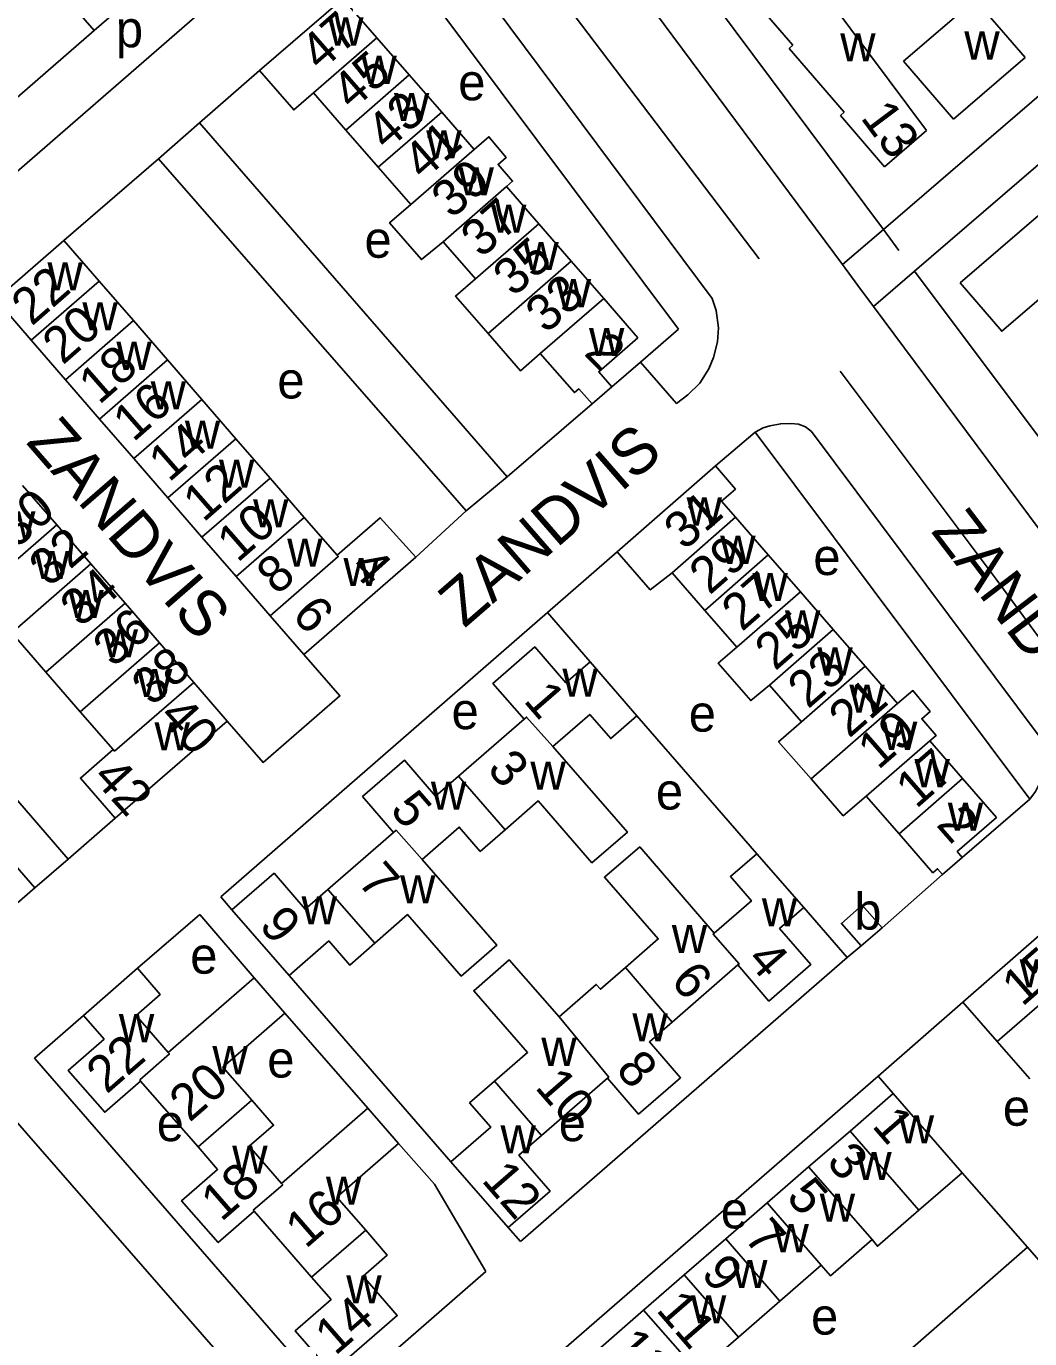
# Model space of a CAD drawing. Extents: x 155854 to 157362, y 383621 to 384685.
# Drawn here: x 156659.8 to 156769.5, y 384304.4 to 384447.9 of the extents above; entities that cross this region are included whole.
import ezdxf

# ---------------------------------------------------------------- set-up
doc = ezdxf.new("R2010")
doc.units = 0
for name, color, linetype in [('BLT_Basislijn', 7, 'Continuous'), ('BLT_Bebouwing', 7, 'Continuous'), ('BLT_Centroide', 7, 'Continuous'), ('BLT_Huisnummer', 7, 'Continuous'), ('BLT_Huisnummer_ tussenligend', 7, 'Continuous'), ('BLT_Huisnummer_reeks', 7, 'Continuous'), ('BLT_Onderverdeling_panden', 7, 'Continuous'), ('BLT_Straatnaam', 7, 'Continuous'), ('BLT_Vlakafsluiter', 7, 'Continuous')]:
    doc.layers.add(name, color=color, linetype=linetype)

msp = doc.modelspace()

# ---------------------------------------------------------------- linework, layer by layer
at = {"layer": 'BLT_Basislijn'}
for p, q in [((156633.62, 384486.24), (156667.24, 384447.45)), ((156708.63, 384463.84), (156739.93, 384422.47)), ((156700.29, 384456.04), (156731.11, 384414.78)), ((156671.77, 384451.38), (156667.24, 384447.45)), ((156667.24, 384447.45), (156655.65, 384437.39)), ((156678.76, 384437.37), (156685.32, 384443.08)), ((156678.76, 384437.37), (156674.26, 384433.43)), ((156678.76, 384437.37), (156712.4, 384398.64)), ((156663.92, 384424.49), (156674.26, 384433.43)), ((156707.92, 384394.91), (156674.26, 384433.43)), ((156749.05, 384421.85), (156753.52, 384425.7)), ((156753.52, 384425.7), (156755.21, 384423.41)), ((156756.91, 384421.13), (156752.44, 384417.28)), ((156752.44, 384417.28), (156750.74, 384419.56)), ((156731.11, 384414.78), (156726.96, 384411.19)), ((156726.96, 384411.19), (156723.82, 384408.47)), ((156721.67, 384406.61), (156712.4, 384398.64)), ((156739.51, 384403.53), (156735.17, 384399.83)), ((156739.51, 384403.53), (156769.52, 384363.37)), ((156712.4, 384398.64), (156707.92, 384394.91)), ((156707.92, 384394.91), (156702.41, 384389.85)), ((156664.38, 384356.83), (156632.56, 384393.62)), ((156716.79, 384383.79), (156724.4, 384390.45)), ((156681.08, 384352.71), (156716.79, 384383.79)), ((156716.79, 384383.79), (156721.46, 384378.4)), ((156726.58, 384372.51), (156739.69, 384357.41)), ((156769.52, 384363.37), (156762.13, 384357.02)), ((156664.38, 384356.83), (156669.55, 384361.31)), ((156660.76, 384353.69), (156664.38, 384356.83)), ((156759.98, 384355.16), (156753.37, 384349.32)), ((156655.52, 384349.15), (156660.76, 384353.69)), ((156682.3, 384351.27), (156681.08, 384352.71)), ((156744.81, 384351.53), (156749.56, 384346.07)), ((156678.79, 384350.78), (156671.96, 384344.89)), ((156684.73, 384343.83), (156678.79, 384350.78)), ((156751.1, 384347.35), (156749.56, 384346.07)), ((156749.56, 384346.07), (156713.84, 384315)), ((156706.24, 384323.72), (156688.55, 384344.09)), ((156697.16, 384329.58), (156688.1, 384339.98)), ((156752.96, 384333.08), (156762.21, 384341.2)), ((156666.07, 384339.74), (156660.71, 384335.07)), ((156660.71, 384335.07), (156693.5, 384297.33)), ((156716.36, 384301.29), (156752.96, 384333.08)), ((156752.96, 384333.08), (156754.6, 384331.19)), ((156656.09, 384331.14), (156688.96, 384293.5)), ((156704.43, 384321.26), (156700.52, 384325.73)), ((156710.07, 384311.72), (156704.43, 384321.26)), ((156762.15, 384322.53), (156769.28, 384314.39)), ((156713.84, 384315), (156712.49, 384316.54)), ((156769.28, 384314.39), (156732.73, 384282.44)), ((156769.28, 384314.39), (156778.23, 384304.02)), ((156693.5, 384297.33), (156710.07, 384311.72))]:
    msp.add_line(p, q, dxfattribs=at)
for points in [[(156749.05, 384421.85), (156709.1, 384475.67)], [(156718.73, 384472.36), (156753.52, 384425.7)], [(156726.96, 384411.19), (156730.91, 384406.67), (156732.14, 384407.62), (156733.47, 384408.89), (156734.43, 384410.44), (156734.94, 384411.69), (156735.4, 384413.39), (156735.49, 384414.94), (156735.24, 384416.83), (156734.81, 384418.13), (156704.77, 384458.46), (156695.52, 384470.73)], [(156648.22, 384422.86), (156694.85, 384463.4), (156691.17, 384468.24)], [(156753.52, 384425.7), (156787.55, 384455)], [(156791.25, 384450.67), (156756.91, 384421.13)], [(156756.91, 384421.13), (156787.78, 384379.92)], [(156783.25, 384376.02), (156775.11, 384386.78), (156752.44, 384417.28)], [(156748.79, 384410.18), (156765.84, 384387.43), (156774.6, 384375.51)], [(156769.52, 384363.37), (156770.14, 384364.24), (156770.6, 384365.09), (156770.91, 384366.62), (156771.02, 384368.53), (156770.93, 384369.3), (156770.65, 384370.13), (156745.65, 384403.58), (156745, 384404.11), (156744.24, 384404.39), (156743.4, 384404.47), (156742.3, 384404.45), (156741.1, 384404.22), (156740.37, 384403.99), (156739.51, 384403.53)], [(156660.76, 384353.69), (156628.85, 384390.4), (156632.56, 384393.62)], [(156681.79, 384371.93), (156685.71, 384367.4), (156694.11, 384374.68), (156690.16, 384379.22)]]:
    msp.add_lwpolyline(points, dxfattribs=at)
at = {"layer": 'BLT_Bebouwing'}
for p, q in [((156694.41, 384450.96), (156685.32, 384443.08)), ((156698.15, 384446.66), (156694.41, 384450.96)), ((156743.61, 384445.84), (156739.35, 384450.78)), ((156763.54, 384450.85), (156755.71, 384444.1)), ((156763.54, 384450.85), (156769.03, 384444.49)), ((156747.93, 384450.33), (156758.25, 384436.52)), ((156701.68, 384442.61), (156698.15, 384446.66)), ((156743.61, 384445.84), (156743.21, 384445.49)), ((156749.23, 384438.51), (156743.21, 384445.49)), ((156755.71, 384444.1), (156761.2, 384437.74)), ((156769.03, 384444.49), (156761.2, 384437.74)), ((156705.23, 384438.52), (156701.68, 384442.61)), ((156691.22, 384440.64), (156694.76, 384436.57)), ((156708.78, 384434.44), (156705.23, 384438.52)), ((156749.23, 384438.51), (156748.82, 384438.15)), ((156753.65, 384432.55), (156748.82, 384438.15)), ((156694.76, 384436.57), (156698.3, 384432.5)), ((156758.25, 384436.52), (156753.65, 384432.55)), ((156698.3, 384432.5), (156701.84, 384428.43)), ((156715.86, 384426.3), (156712.32, 384430.38)), ((156719.4, 384422.23), (156715.86, 384426.3)), ((156663.92, 384424.49), (156656.48, 384418.02)), ((156705.38, 384424.36), (156708.92, 384420.29)), ((156722.95, 384418.16), (156719.4, 384422.23)), ((156726.68, 384413.86), (156722.95, 384418.16)), ((156723.82, 384408.47), (156721.67, 384406.61)), ((156735.17, 384399.83), (156724.4, 384390.45)), ((156659.4, 384397.71), (156663.17, 384393.38)), ((156663.17, 384393.38), (156666.88, 384389.11)), ((156666.88, 384389.11), (156670.61, 384384.81)), ((156670.61, 384384.81), (156674.38, 384380.47)), ((156674.38, 384380.47), (156678.12, 384376.16)), ((156665.72, 384372.95), (156661.96, 384377.29)), ((156678.12, 384376.16), (156681.79, 384371.93)), ((156681.79, 384371.93), (156669.55, 384361.31)), ((156739.69, 384357.41), (156744.81, 384351.53)), ((156688.55, 384344.09), (156682.3, 384351.27)), ((156753.37, 384349.32), (156751.1, 384347.35)), ((156770.85, 384348.72), (156762.21, 384341.2)), ((156671.96, 384344.89), (156666.07, 384339.74)), ((156749.88, 384327.09), (156754.6, 384331.19)), ((156754.6, 384331.19), (156762.15, 384322.53)), ((156745.34, 384323.16), (156749.88, 384327.09)), ((156712.49, 384316.54), (156706.24, 384323.72)), ((156740.81, 384319.22), (156745.34, 384323.16)), ((156736.29, 384315.29), (156740.81, 384319.22)), ((156731.75, 384311.35), (156736.29, 384315.29)), ((156727.31, 384307.49), (156731.75, 384311.35)), ((156722.63, 384303.43), (156727.31, 384307.49))]:
    msp.add_line(p, q, dxfattribs=at)
for points in [[(156685.32, 384443.08), (156689.06, 384438.77), (156691.22, 384440.64)], [(156712.32, 384430.38), (156712.99, 384430.96), (156711.39, 384432.8), (156712.29, 384433.57), (156710.39, 384435.84), (156708.78, 384434.44)], [(156761.92, 384419.87), (156770.48, 384427.24), (156771.78, 384425.72), (156777.01, 384430.22), (156784.81, 384421.15), (156783.66, 384420.16), (156787.79, 384415.39), (156781.74, 384410.16), (156773.05, 384420.23), (156766.46, 384414.57), (156761.91, 384419.87)], [(156701.84, 384428.43), (156699.53, 384426.43), (156703.02, 384422.4), (156705.38, 384424.36)], [(156667.79, 384420.03), (156663.92, 384424.49)], [(156708.92, 384420.29), (156706.75, 384418.41), (156710.3, 384414.32)], [(156671.53, 384415.72), (156667.79, 384420.03)], [(156656.48, 384418.02), (156660.35, 384413.57)], [(156675.27, 384411.42), (156671.53, 384415.72)], [(156660.35, 384413.57), (156664.09, 384409.25)], [(156710.3, 384414.32), (156713.84, 384410.24), (156716.01, 384412.13)], [(156726.68, 384413.86), (156722.4, 384410.13), (156723.82, 384408.47)], [(156716.01, 384412.13), (156719.74, 384407.85), (156720.21, 384408.26), (156721.67, 384406.61)], [(156679, 384407.11), (156675.27, 384411.42)], [(156664.09, 384409.25), (156667.82, 384404.95)], [(156682.74, 384402.81), (156679, 384407.11)], [(156667.82, 384404.95), (156671.56, 384400.65)], [(156686.47, 384398.51), (156682.74, 384402.81)], [(156671.56, 384400.65), (156675.29, 384396.34)], [(156737.37, 384394.22), (156735.83, 384395.98), (156737.35, 384397.3), (156735.17, 384399.83)], [(156690.2, 384394.21), (156686.47, 384398.51)], [(156675.29, 384396.34), (156679.02, 384392.04)], [(156693.8, 384390.06), (156690.2, 384394.21)], [(156702.41, 384389.85), (156698.52, 384394.16), (156693.8, 384390.06)], [(156740.94, 384390.1), (156737.37, 384394.22)], [(156679.02, 384392.04), (156682.76, 384387.74)], [(156724.4, 384390.45), (156728.03, 384386.28), (156730.41, 384388.14)], [(156744.44, 384386.07), (156740.94, 384390.1)], [(156690.16, 384379.22), (156702.41, 384389.85)], [(156682.76, 384387.74), (156686.49, 384383.44)], [(156730.41, 384388.14), (156733.99, 384384.02)], [(156748.03, 384381.94), (156744.44, 384386.07)], [(156686.49, 384383.44), (156690.16, 384379.22)], [(156733.99, 384384.02), (156737.49, 384380)], [(156661.96, 384377.29), (156658.22, 384381.59)], [(156751.51, 384377.93), (156748.03, 384381.94)], [(156714.23, 384372.12), (156710.83, 384376.04), (156715.41, 384380.03), (156718.82, 384376.11), (156721.46, 384378.4)], [(156737.49, 384380), (156735.47, 384378.25), (156739.02, 384374.17), (156741.08, 384375.86)], [(156721.46, 384378.4), (156726.58, 384372.51)], [(156755.05, 384373.85), (156751.51, 384377.93)], [(156741.08, 384375.86), (156744.56, 384371.86)], [(156758.6, 384369.77), (156759.3, 384370.35), (156757.71, 384372.18), (156758.62, 384372.98), (156756.74, 384375.27), (156755.05, 384373.85)], [(156669.33, 384368.8), (156665.72, 384372.95)], [(156707.07, 384365.9), (156714.23, 384372.12)], [(156726.58, 384372.51), (156723.71, 384370.02), (156721.41, 384372.66), (156717.37, 384369.14)], [(156744.56, 384371.86), (156742.07, 384369.67), (156745.61, 384365.6)], [(156669.55, 384361.31), (156665.74, 384365.69), (156669.33, 384368.8)], [(156717.37, 384369.14), (156725.53, 384359.76), (156721.66, 384356.43), (156715.79, 384363.19), (156712.17, 384360.04)], [(156762.18, 384365.64), (156758.6, 384369.77)], [(156699.97, 384359.74), (156696.59, 384363.66), (156701.17, 384367.65), (156704.56, 384363.72), (156707.07, 384365.9)], [(156745.61, 384365.6), (156749.14, 384361.57), (156751.65, 384363.7)], [(156762.13, 384357.02), (156761.59, 384357.65), (156765.88, 384361.39), (156762.18, 384365.64)], [(156751.65, 384363.7), (156755.24, 384359.58)], [(156712.17, 384360.04), (156709.45, 384357.68), (156707.15, 384360.33), (156703.09, 384356.8)], [(156692.8, 384353.52), (156699.97, 384359.74)], [(156755.24, 384359.58), (156758.93, 384355.33), (156759.44, 384355.78), (156759.98, 384355.16)], [(156725.33, 384344.99), (156728.9, 384348.11), (156723.02, 384354.84), (156726.88, 384358.17), (156735.01, 384348.74)], [(156735.01, 384348.74), (156739.1, 384352.26), (156736.8, 384354.92), (156739.69, 384357.41)], [(156703.09, 384356.8), (156711.25, 384347.4), (156707.37, 384344.03), (156701.5, 384350.76), (156697.92, 384347.63)], [(156759.98, 384355.16), (156762.13, 384357.02)], [(156682.3, 384351.27), (156686.91, 384355.28), (156690.3, 384351.34), (156692.8, 384353.52)], [(156744.81, 384351.53), (156742.18, 384349.24), (156745.59, 384345.31), (156741.01, 384341.31), (156737.62, 384345.26)], [(156751.1, 384347.35), (156748.93, 384349.8), (156751.21, 384351.81), (156753.37, 384349.32)], [(156697.92, 384347.63), (156695.18, 384345.24), (156692.89, 384347.88), (156688.55, 384344.09)], [(156711.01, 384332.54), (156714.62, 384335.68), (156708.73, 384342.44), (156712.61, 384345.81), (156718.06, 384339.58)], [(156675.34, 384335.68), (156671.82, 384339.74), (156674.46, 384342.03), (156671.96, 384344.89)], [(156718.06, 384339.58), (156722.12, 384343.13), (156722.59, 384342.59), (156725.33, 384344.99)], [(156737.62, 384345.26), (156730.41, 384338.99)], [(156684.73, 384343.83), (156675.34, 384335.68)], [(156688.1, 384339.98), (156684.73, 384343.83)], [(156684.47, 384330.46), (156681.32, 384334.08), (156688.1, 384339.98)], [(156762.21, 384341.2), (156765.97, 384336.89)], [(156666.07, 384339.74), (156668.33, 384337.14), (156664.41, 384333.72), (156668.4, 384329.14), (156672.32, 384332.56)], [(156730.41, 384338.99), (156727.94, 384336.84), (156731.35, 384332.91), (156726.76, 384328.92), (156723.35, 384332.86)], [(156765.97, 384336.89), (156769.52, 384332.81)], [(156723.35, 384332.86), (156716.16, 384326.61)], [(156672.32, 384332.56), (156678.6, 384325.35)], [(156706.24, 384323.72), (156710.59, 384327.51), (156708.28, 384330.16), (156711.01, 384332.54)], [(156687.73, 384321.35), (156684.19, 384325.42), (156686.85, 384327.73), (156684.47, 384330.46)], [(156697.16, 384329.58), (156687.73, 384321.35)], [(156700.52, 384325.73), (156697.16, 384329.58)], [(156696.92, 384316.23), (156693.77, 384319.85), (156700.52, 384325.73)], [(156716.16, 384326.61), (156713.67, 384324.45), (156717.08, 384320.53), (156712.49, 384316.54)], [(156678.6, 384325.35), (156680.73, 384322.9), (156676.8, 384319.46), (156680.8, 384314.88), (156684.72, 384318.32)], [(156762.15, 384322.53), (156757.41, 384318.42)], [(156757.41, 384318.42), (156752.87, 384314.49), (156752.3, 384315.22)], [(156684.72, 384318.32), (156691, 384311.11)], [(156691, 384311.11), (156693.13, 384308.67), (156689.21, 384305.22), (156693.2, 384300.69), (156700.38, 384306.91), (156696.63, 384311.23), (156699.27, 384313.53), (156696.92, 384316.23)], [(156752.3, 384315.22), (156747.73, 384311.27), (156746.72, 384312.41)], [(156746.72, 384312.41), (156742.2, 384308.48)], [(156742.2, 384308.48), (156737.67, 384304.55)], [(156737.67, 384304.55), (156733.26, 384300.72)]]:
    msp.add_lwpolyline(points, dxfattribs=at)
at = {"layer": 'BLT_Onderverdeling_panden'}
for p, q in [((156698.15, 384446.66), (156691.22, 384440.64)), ((156701.68, 384442.61), (156694.76, 384436.57)), ((156705.23, 384438.52), (156698.3, 384432.5)), ((156719.4, 384422.23), (156710.3, 384414.32)), ((156660.35, 384413.57), (156667.79, 384420.03)), ((156664.09, 384409.25), (156671.53, 384415.72)), ((156667.82, 384404.95), (156675.27, 384411.42)), ((156671.56, 384400.65), (156679, 384407.11)), ((156675.29, 384396.34), (156682.74, 384402.81)), ((156679.02, 384392.04), (156686.47, 384398.51)), ((156663.17, 384393.38), (156656.22, 384387.34)), ((156682.76, 384387.74), (156690.2, 384394.21)), ((156737.37, 384394.22), (156730.41, 384388.14)), ((156740.94, 384390.1), (156733.99, 384384.02)), ((156666.88, 384389.11), (156658.22, 384381.59)), ((156744.44, 384386.07), (156737.49, 384380)), ((156670.61, 384384.81), (156661.96, 384377.29)), ((156748.03, 384381.94), (156741.08, 384375.86)), ((156674.38, 384380.47), (156665.72, 384372.95)), ((156751.51, 384377.93), (156744.56, 384371.86)), ((156755.05, 384373.85), (156745.61, 384365.6)), ((156758.6, 384369.77), (156751.65, 384363.7)), ((156712.17, 384360.04), (156707.07, 384365.9)), ((156762.18, 384365.64), (156755.24, 384359.58)), ((156697.92, 384347.63), (156692.8, 384353.52)), ((156730.41, 384338.99), (156725.33, 384344.99)), ((156765.97, 384336.89), (156774.6, 384344.4)), ((156716.16, 384326.61), (156711.01, 384332.54)), ((156678.6, 384325.35), (156684.47, 384330.46)), ((156757.41, 384318.42), (156749.88, 384327.09)), ((156752.3, 384315.22), (156745.34, 384323.16)), ((156691, 384311.11), (156696.92, 384316.23)), ((156742.2, 384308.48), (156736.29, 384315.29)), ((156737.67, 384304.55), (156731.75, 384311.35)), ((156733.26, 384300.72), (156727.31, 384307.49))]:
    msp.add_line(p, q, dxfattribs=at)
for points in [[(156708.78, 384434.44), (156701.84, 384428.43)], [(156712.32, 384430.38), (156705.38, 384424.36)], [(156715.86, 384426.3), (156708.92, 384420.29)], [(156722.95, 384418.16), (156716.01, 384412.13)], [(156686.49, 384383.44), (156693.92, 384389.92), (156693.8, 384390.06)], [(156678.12, 384376.16), (156669.47, 384368.64), (156669.33, 384368.8)], [(156717.37, 384369.14), (156714.52, 384372.37), (156714.23, 384372.12)], [(156703.09, 384356.8), (156700.25, 384359.98), (156699.97, 384359.74)], [(156737.62, 384345.26), (156737.75, 384345.37), (156734.9, 384348.63), (156735.01, 384348.74)], [(156723.35, 384332.86), (156723.5, 384332.99), (156718.06, 384339.58)], [(156672.32, 384332.56), (156672.24, 384332.68), (156675.46, 384335.53), (156675.34, 384335.68)], [(156684.72, 384318.32), (156684.62, 384318.43), (156687.86, 384321.21), (156687.73, 384321.35)], [(156746.72, 384312.41), (156740.81, 384319.22)]]:
    msp.add_lwpolyline(points, dxfattribs=at)
at = {"layer": 'BLT_Vlakafsluiter'}
msp.add_line((156750.74, 384419.56), (156749.05, 384421.85), dxfattribs=at)

# ---------------------------------------------------------------- texts
at = {"layer": 'BLT_Centroide'}
for s, p in [('p', (156669.61, 384445.62)), ('w', (156692.81, 384445.81)), ('w', (156748.8, 384444.08)), ('w', (156762.37, 384444.28)), ('w', (156696.45, 384441.62)), ('e', (156707.04, 384439.82)), ('w', (156700.01, 384437.56)), ('w', (156703.54, 384433.47)), ('w', (156707.07, 384429.41)), ('w', (156710.62, 384425.34)), ('e', (156696.79, 384422.6)), ('w', (156714.16, 384421.25)), ('w', (156662.13, 384419.03)), ('w', (156717.7, 384417.19)), ('w', (156665.95, 384414.66)), ('w', (156721.34, 384411.86)), ('w', (156669.67, 384410.34)), ('e', (156687.26, 384407.21)), ('w', (156673.41, 384406.03)), ('w', (156677.15, 384401.72)), ('w', (156680.88, 384397.44)), ('w', (156684.61, 384393.12)), ('w', (156732.01, 384393.31)), ('w', (156656.95, 384391.78)), ('w', (156688.34, 384388.81)), ('w', (156735.68, 384389.12)), ('w', (156660.7, 384387.47)), ('e', (156745.86, 384387.9)), ('w', (156694.49, 384386.69)), ('w', (156739.21, 384385.06)), ('w', (156664.41, 384383.19)), ('w', (156742.76, 384380.97)), ('w', (156668.16, 384378.88)), ('w', (156746.3, 384376.91)), ('w', (156671.92, 384374.56)), ('w', (156718.43, 384374.59)), ('w', (156749.8, 384372.84)), ('e', (156706.31, 384371.04)), ('e', (156732.24, 384370.77)), ('w', (156673.84, 384368.72)), ('w', (156753.36, 384368.78)), ('w', (156714.93, 384364.41)), ('w', (156756.92, 384364.69)), ('w', (156704.05, 384362.22)), ('e', (156728.65, 384362.25)), ('w', (156760.56, 384359.94)), ('w', (156700.68, 384352)), ('b', (156750.34, 384349.12)), ('w', (156689.91, 384349.69)), ('w', (156740.23, 384349.48)), ('w', (156730.39, 384346.56)), ('e', (156677.74, 384344.3)), ('w', (156768.41, 384342.81)), ('w', (156669.94, 384336.8)), ('w', (156726.08, 384336.89)), ('w', (156716.12, 384334.22)), ('w', (156680.17, 384333.3)), ('e', (156686.16, 384332.94)), ('e', (156766.58, 384327.67)), ('e', (156674.08, 384325.98)), ('e', (156718.03, 384325.98)), ('w', (156755.2, 384325.73)), ('w', (156711.66, 384324.64)), ('w', (156682.33, 384322.41)), ('w', (156750.56, 384321.73)), ('w', (156692.58, 384319.02)), ('w', (156746.56, 384317.17)), ('e', (156735.74, 384316.44)), ('w', (156741.5, 384313.84)), ('w', (156736.98, 384309.92)), ('w', (156694.8, 384308.23)), ('w', (156732.48, 384306.05)), ('e', (156745.61, 384304.83))]:
    msp.add_text(s, height=4, dxfattribs=at).set_placement(p)
at = {"layer": 'BLT_Huisnummer'}
for s, rotation, p in [('47', 41.1425, (156691.98, 384442.89)), ('43', 41.1425, (156699.23, 384434.2)), ('13', 306.8181, (156750.94, 384437.9)), ('39', 41.1425, (156706.33, 384426.77)), ('35', 41.1425, (156713.07, 384418.23)), ('22', 41.2107, (156660.41, 384415.05)), ('2', 314.3142, (156720.68, 384412.08)), ('18', 41.2107, (156667.78, 384406.44)), ('14', 41.2107, (156675.42, 384397.96)), ('31', 41.1441, (156731.76, 384390.5)), ('10', 41.2107, (156682.91, 384389.17)), ('32', 40.9816, (156662.34, 384386.49)), ('27', 41.1441, (156738.06, 384381.63)), ('36', 40.9816, (156669.33, 384377.69)), ('23', 41.1441, (156745.28, 384373.18)), ('1', 310.9766, (156714.08, 384374.12)), ('19', 41.1441, (156752.95, 384366.51)), ('5', 310.9766, (156699.47, 384362.14)), ('2', 311.1424, (156759.2, 384360.55)), ('9', 310.9766, (156685.15, 384349.51)), ('15', 41.144, (156768.7, 384340.61)), ('4', 310.9921, (156738.46, 384345.74)), ('22', 40.984, (156668.6, 384331.06)), ('8', 310.9921, (156724.15, 384333.72)), ('1', 310.9802, (156752.17, 384327.62)), ('18', 40.984, (156681.13, 384317.08)), ('12', 310.9921, (156709.49, 384321.66)), ('5', 310.9802, (156742.79, 384319.8)), ('9', 310.9802, (156733.47, 384311.41)), ('14', 40.984, (156693.59, 384302.44))]:
    msp.add_text(s, height=4, rotation=rotation, dxfattribs=at).set_placement(p)
at = {"layer": 'BLT_Huisnummer_ tussenligend'}
for s, rotation, p in [('45', 41.1425, (156695.44, 384438.62)), ('41', 41.1425, (156703.23, 384430.96)), ('37', 41.1425, (156709.55, 384422.48)), ('33', 41.1425, (156716.62, 384414.21)), ('20', 41.2107, (156663.81, 384410.8)), ('16', 41.2107, (156671.52, 384402.36)), ('12', 41.2107, (156679.18, 384393.58)), ('30', 40.9816, (156658.74, 384390.71)), ('29', 41.1441, (156734.52, 384385.64)), ('8', 41.2107, (156687.23, 384385.6)), ('34', 40.9816, (156665.74, 384382.08)), ('25', 41.1441, (156741.69, 384377.34)), ('38', 40.9816, (156673.56, 384373.46)), ('21', 41.1441, (156749.77, 384369.98)), ('3', 310.9766, (156710.09, 384366.61)), ('17', 41.1441, (156757.1, 384362.26)), ('7', 310.9766, (156695.92, 384354.29)), ('6', 310.9921, (156730.14, 384343.43)), ('20', 40.984, (156677.67, 384327.97)), ('10', 310.9921, (156715.33, 384331.83)), ('3', 310.9802, (156747.18, 384323.65)), ('16', 40.984, (156690.36, 384314.14)), ('7', 310.9802, (156738.16, 384315.34)), ('11', 310.9802, (156728.58, 384307.48)), ('13', 310.9802, (156723.67, 384303.35))]:
    msp.add_text(s, height=4, rotation=rotation, dxfattribs=at).set_placement(p)
at = {"layer": 'BLT_Huisnummer_reeks'}
for s, rotation, p in [('4', 312.0599, (156695.1, 384388.65)), ('6', 310.9624, (156688.74, 384383.45)), ('40', 312.0599, (156674.19, 384372.35)), ('42', 312.0599, (156666.94, 384365.67))]:
    msp.add_text(s, height=4, rotation=rotation, dxfattribs=at).set_placement(p)
at = {"layer": 'BLT_Straatnaam'}
for s, rotation, p in [('ZANDVIS', 310.9816, (156659.7, 384402.37)), ('ZANDVIS', 40.9824, (156707.71, 384382.02)), ('ZANDSCHUIT', 307.2809, (156758.65, 384392.66))]:
    msp.add_text(s, height=5, rotation=rotation, dxfattribs=at).set_placement(p)

doc.saveas('drawing.dxf')
